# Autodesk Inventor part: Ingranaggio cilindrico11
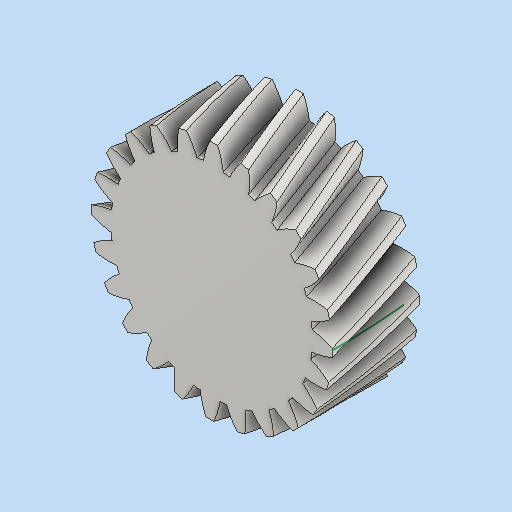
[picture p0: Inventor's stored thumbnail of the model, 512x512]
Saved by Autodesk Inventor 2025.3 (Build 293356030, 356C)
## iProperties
CustomPartVersion: 1
Created: 2025-12
Part Number: Ingranaggio cilindrico11
Material: Steel
Document SubType Name: Modeling
Designer: R5800u
Categories: <?xml version="1.0" encoding="UTF-16"?> <MemberInstance><Categories><FamilyTemplate><FamilyTemplateParameter ValueType="xs:double" Id="1" ObjectReferenceKey="da
Density: 1 g/cm^3
Appearance: Steel
Author: R5800u
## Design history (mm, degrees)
sketch "Sketch1"
  geometry: C1 r 13.732 at (0, 0)
  constraints: 1 centre point
  dimensions: "d0" = 27.46478 diameter of C1 (= da_da)
extrude "Extrusion1" new body sketch "Sketch1" distance "d1" = 10 (= da_b); taper "d2" = 0 deg
workplane "Work Plane2"
feature "Diametro primitivo" dims "d4" = 10, "d5" = 0
workplane "Work Plane8"
workplane "Work Plane9"
feature "Ingranaggio cilindrico" dims "da_b" = 10, "da_d" = 25.46478, "da_aw" = 25.46478, "da_da" = 27.46478, "da_df" = 22.96478, "da_dw" = 25.46478, angle "da_beta" = 19.528 deg, "da_lefttooth" = 10, "da_righttooth" = 0
sketch "Schizzo3" dims "d51" = 14
  geometry: L1 (0, 0)-(0, 7); 2 further points
  constraints: 2 coincident, 2 end point, 1 vertical, 1 vertical alignment, 2 other
hole "Foro1" sketch "Schizzo3" at (0, 7) diameter "d52" = 3.2; stored, may be unused: countersink angle "d56" = 90 deg, drill point angle "d58" = 118 deg; dims "d53" = 6, "d54" = 5.5, "d55" = 3, "d57" = 11
pattern_circular "Serie circolare1" dims angle "d60" = 360 deg
sketch "Schizzo4"
  geometry: 3 further points
  constraints: 1 other
body "Solid1"
sketch "Sketch2"
  geometry: C1 r 13.732 at (0, 0) reference; C2 r 12.732 at (0, 0)
  constraints: 1 centre point, 1 coincident
  dimensions: "d3" = 25.46478 diameter of C2 (= da_d)
body "Srf1"
other parameters: "d16" = 25.46478 (= da_aw), "d17" = 0, "d34" = 7.5 deg (computed from da_z), "d39" = 0, "d41" = 0, "d43" = 25.46478 (= da_aw), "d46" = 25.46478 (= da_aw), "d47" = 0, "d48" = 0
